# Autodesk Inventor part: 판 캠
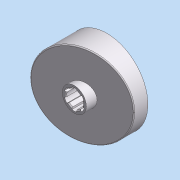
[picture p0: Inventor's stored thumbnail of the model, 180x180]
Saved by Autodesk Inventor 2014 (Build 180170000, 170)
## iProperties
Created: 2012-05
Part Number: 판 캠
Document SubType Name: 모델링
Designer: SeoGD™
Material: 강철
Mass: 681.587 g
Surface Area: 331.303 cm^2
Volume: 86.8264 cm^3
Density: 7.85 g/cm^3
Appearance: 알루미늄 - 평지
변환 표준: STEP AP214IS
파일 이름: C:\Users\SeoGD\Desktop\?쒗뿕\??stp
전처리기: Build: 253, Release: 2010 SP1 - Date: Wed 07/29/2009
전송 단위: 밀리미터
불확실성: 0.01
Author: SeoGD™
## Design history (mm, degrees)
node "작업 평면4"
sketch "스케치1"
  geometry: C1 r 44.5 at (0, 0); 1 further point
  constraints: 1 centre point, 1 coincident
  dimensions: "d25" = 89 diameter of C1
extrude "돌출1" new body sketch "스케치1" distance "d1" = 40; taper "d2" = 0 deg
sketch "스케치2"
  geometry: L1 (-44.5, 15)-(44.5, 38.847); L2 (-44.5, 0)-(-44.5, 40) reference; L3 (-44.5, 40)-(44.5, 40) reference; L4 (44.5, 0)-(44.5, 40) reference; 1 further point
  constraints: 2 end point, 2 point on line
  dimensions: "d26" = 15 distance of L2.start L1.start; "d27" = 75 deg angle of L1 L2
extrude "돌출2" cut sketch "스케치2" stored distance "d5" = 40; taper "d6" = 0 deg
node "작업 평면1"
sketch "스케치3"
  geometry: C1 r 13 at (0, 0); 1 further point
  constraints: 1 centre point, 1 coincident
  dimensions: "d9" = 26 diameter of C1
extrude "돌출3" join sketch "스케치3" distance "d10" = 38; taper "d11" = 0 deg
hole "구멍1" diameter "d14" = 18; stored, may be unused: countersink angle "d18" = 90 deg, drill point angle "d20" = 118 deg; dims "d12" = 10, "d13" = 10, "d15" = 6, "d16" = 4, "d17" = 2, "d19" = 8
feature "쉘2" dims "d29" = 5
sketch "스케치6"
  geometry: C1 r 17.5 at (0, 0); C2 r 14 at (0, 0) reference; 1 further point
  constraints: 1 centre point, 1 coincident
  dimensions: "d28" = 35 diameter of C1
extrude "돌출4" join sketch "스케치6" stored distance "d30" = 38; taper "d31" = 0 deg
fillet "모깎기1" dims "d32" = 3
chamfer "모따기1" distance "d21" = 1; stored, may be unused: second distance "d22" = 2, angle "d23" = 45 deg
sketch "스케치7"
  geometry: L1 (-12.374, 12.374)-(-27.931, 27.931); A1 r 39.5 centre (0, 0) between (-27.931, 27.931) and (0, 39.5) reference; 2 further points
  constraints: 2 end point, 2 point on circle, 1 point on line, 1 vertical alignment, 2 other
  dimensions: "d33" = 45 deg dimension on point (0, 0) L1.start A1.end
feature "리브1" sketch "스케치7" dims "d34" = 5, "d35" = 1, "d36" = 0
fillet "모깎기2" dims "d37" = 3
sketch "스케치8"
  geometry: L1 (2.5, 10.712)-(2.5, 8.646); L2 (-2.5, 10.712)-(-2.5, 8.646); A1 r 11 centre (0, 0) between (2.5, 10.712) and (-2.5, 10.712); A2 r 9 centre (0, 0) between (2.5, 8.646) and (-2.5, 8.646) reference; 1 further point
  constraints: 4 end point, 4 point on circle, 2 parallel, 1 centre point, 1 coincident, 1 vertical
  dimensions: "d41" = 22 diameter of A1; "d42" = 5 distance between parallel lines of L1 L2
extrude "돌출5" cut sketch "스케치8" stored distance "d43" = 38; taper "d44" = 0 deg
fillet "모깎기3" dims "d48" = 1
node "솔리드1"
node "솔리드 본체"
node "곡면 본체"
pattern_circular "원형 패턴1" dims angle "d39" = 360 deg
pattern_circular "원형 패턴2" dims angle "d46" = 360 deg
node "솔리드2"
